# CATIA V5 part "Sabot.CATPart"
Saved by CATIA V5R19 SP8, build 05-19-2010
Part number: Sabot
Bounding box of the stored display mesh (mm): x -145 to 145, y -95.99 to 104.01, z -1620.007 to -890.007
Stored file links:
  G:\EU_thinkMotion\CFAO_2010\MMS_groupe3\MMS_groupe3\rdalborgo\rdalborgo\Sabot.CATPart
  G:\EU_thinkMotion\CFAO_2010\MMS_groupe3\MMS_groupe3\rdalborgo\rdalborgo\rdalborgo.CATProduct
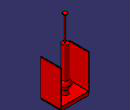
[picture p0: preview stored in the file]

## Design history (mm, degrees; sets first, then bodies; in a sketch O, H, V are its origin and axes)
External parameters (linked from other documents)
  `External.X Sabot` = 270 mm
  `External.X Cremaillere` = 330 mm
  `External.Y Sabot` = 200 mm
Set1
  Plane1: linked copy from another document
  Point1: linked copy from another document
  Point2 "B verin frein": linked copy from another document
  Line1: linked copy from another document
Body1 (main body)
  Sketch1 on Plane1, origin (0, 4.0096, 0), H (-1, 0, 0), V (0, 0, 1)
    line L1 (-135, -1620.0067) -> (135, -1620.0067)
    line L2 (135, -1620.0067) -> (135, -1600.0067)
    line L3 (135, -1600.0067) -> (145, -1600.0067)
    line L4 (145, -1600.0067) -> (145, -1250.0067)
    line L5 (145, -1250.0067) -> (135, -1250.0067)
    point P6 (135, -1250.0067)
    line L6 (135, -1250.0067) -> (135, -1585.0067)
    line L7 (135, -1585.0067) -> (-135, -1585.0067)
    line L8 (-135, -1585.0067) -> (-135, -1250.0067)
    point P9 (-135, -1250.0067)
    line L9 (-135, -1250.0067) -> (-145, -1250.0067)
    line L10 (-145, -1250.0067) -> (-145, -1600.0067)
    point P11 (-145, -1600.0067)
    line L11 (-145, -1600.0067) -> (-135, -1600.0067)
    point P12 (-135, -1600.0067)
    line L12 (-135, -1600.0067) -> (-135, -1620.0067)
    reference projected point E1 (0, -1620.0067) from Point1
    reference projected point E2 (0, -1620.0067) from Point1
    distance L12 L2 = 270 {= `External.X Sabot`}
    distance L11 L7 = 15
    distance L8 L10 = 10
    distance L6 L4 = 10
    distance L5 L3 = 350
    distance L2 E1 = 135 {= `External.X Sabot` /2}
    distance L11 L1 = 20
    horizontal: L1 H, L3 H, L5 H, L7 H, L9 H, L11 H
    vertical: L2 V, L4 V, L6 V, L8 V, L10 V, L12 V
    coincidence: P6 L2, P9 L5, P11 L3, P12 L8, L2 L6, L12 L8, L1 E2
  Pad1: profile Sketch1, direction (0, 1, 0), length 100 {= `External.Y Sabot` /2}, mirrored extent
  Sketch2 on Plane1, origin (0, 4.0096, 0), H (-1, 0, 0), V (0, 0, 1)
    arc A1 centre (0, -1500.0067) radius 50 from (50, -1500.0067) to (30, -1460.0067) ccw
    point P1 (0, -1500.0067)
    reference projected point E1 (0, -1500.0067) from Point2
    point P2 (30, -1540.0067)
    line L1 (30, -1540.0067) -> (30, -1585.0067)
    line L2 (30, -1585.0067) -> (0, -1585.0067)
    point P4 (0, -1585.0067)
    line L3 (0, -1585.0067) -> (0, -890.0067)
    line L4 (0, -890.0067) -> (20, -890.0067)
    line L5 (20, -890.0067) -> (20, -900.0067)
    line L6 (20, -900.0067) -> (5, -900.0067)
    line L7 (5, -900.0067) -> (5, -1150.0067)
    line L8 (5, -1150.0067) -> (30, -1150.0067)
    line L9 (30, -1150.0067) -> (30, -1460.0067)
    point P11 (30, -1460.0067)
    reference projected line E2 (0, -1300) -> (0, -1620) from Line1
    reference projected point E3 (0, -1620.0067) from Point1
    reference projected point E4 (0, -1620.0067) from Point1
    reference projected point E5 (0, -1620.0067) from Point1
    point P12 (50, -1500.0067)
    point P13 (50, -1500.0067)
    arc A2 centre (0, -1500.0067) radius 50 from (30, -1540.0067) to (50, -1500.0067) ccw
    radius A1 = 50
    distance L6 L4 = 10
    distance L5 L3 = 20
    distance P4 E3 = 35
    distance L3 L1 = 30
    distance L3 L9 = 30
    distance L3 L7 = 5
    distance L8 E4 = 470
    distance L4 E5 = 730
    coincidence: P1 E1, P2 A1, P11 A1, L3 E2, P12 P13
    vertical: L1 V, L3 V, L5 V, L7 V
    horizontal: L2 H, L4 H, L6 H, L8 H
  Shaft1: profile Sketch2, axis Line1, angle 360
